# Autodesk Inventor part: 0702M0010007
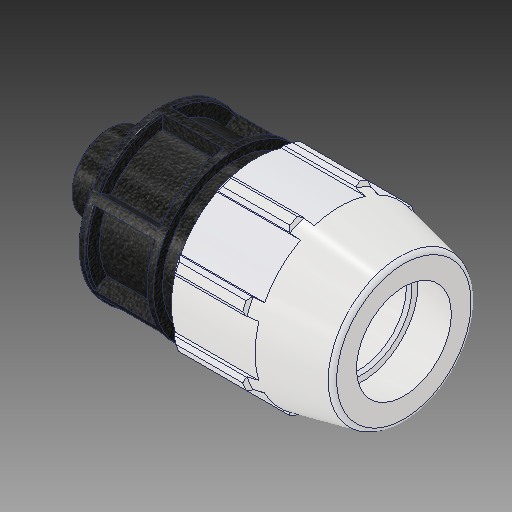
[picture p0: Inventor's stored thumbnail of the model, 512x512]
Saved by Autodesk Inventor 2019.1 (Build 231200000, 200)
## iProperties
Created: 2017-02
Part Number: 0702M0010007
Material: PVC-Piping
Description: PLASSON MALE ADAPTOR 1'' - 3/4''M
Document SubType Name: Modeling
Designer: KIM
Mass: 92.6774 g
Surface Area: 199.44 cm^2
Volume: 66.1981 cm^3
Density: 1.4 g/cm^3
Appearance: PTFE
Author: KIM
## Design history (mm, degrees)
derived "0702M0.ipt"
feature "Solid1::0702M0.ipt"
tag "TaggingFeature1"
body "Solid1"
other parameters: "d2" = 33.3, "d4" = 14.84086, "d5" = 25.9715, "d7" = 64.008, "d8" = 48.006, "d9" = 14.84086, "d11" = 2.96817, "d12" = 51.2064, "d13" = 120 deg, "d14" = 49.95, "d15" = 12 deg, "d16" = 57.6072, "d18" = 1.665, "d19" = 35 deg, "d20" = 17.5 deg, "d21" = 59.52744, "d23" = 0, "d25" = 360 deg, "d27" = 1.28016, "d34" = 3.2004, "d36" = 0, "d42" = 25.9715, "d43" = 1.92024, "d46" = 0.999, "d49" = 82.042, "d51" = 103.886, "d52" = 18.034, "d53" = 0.666, "d55" = 360 deg, "d57" = 26.441, "d58" = 18.5087, "d59" = 20.7772, "d_" = 33.3, "E_" = 64.008, "H_" = 103.886, "l_" = 82.042, "l_2" = 18.034, "G_" = 26.441
